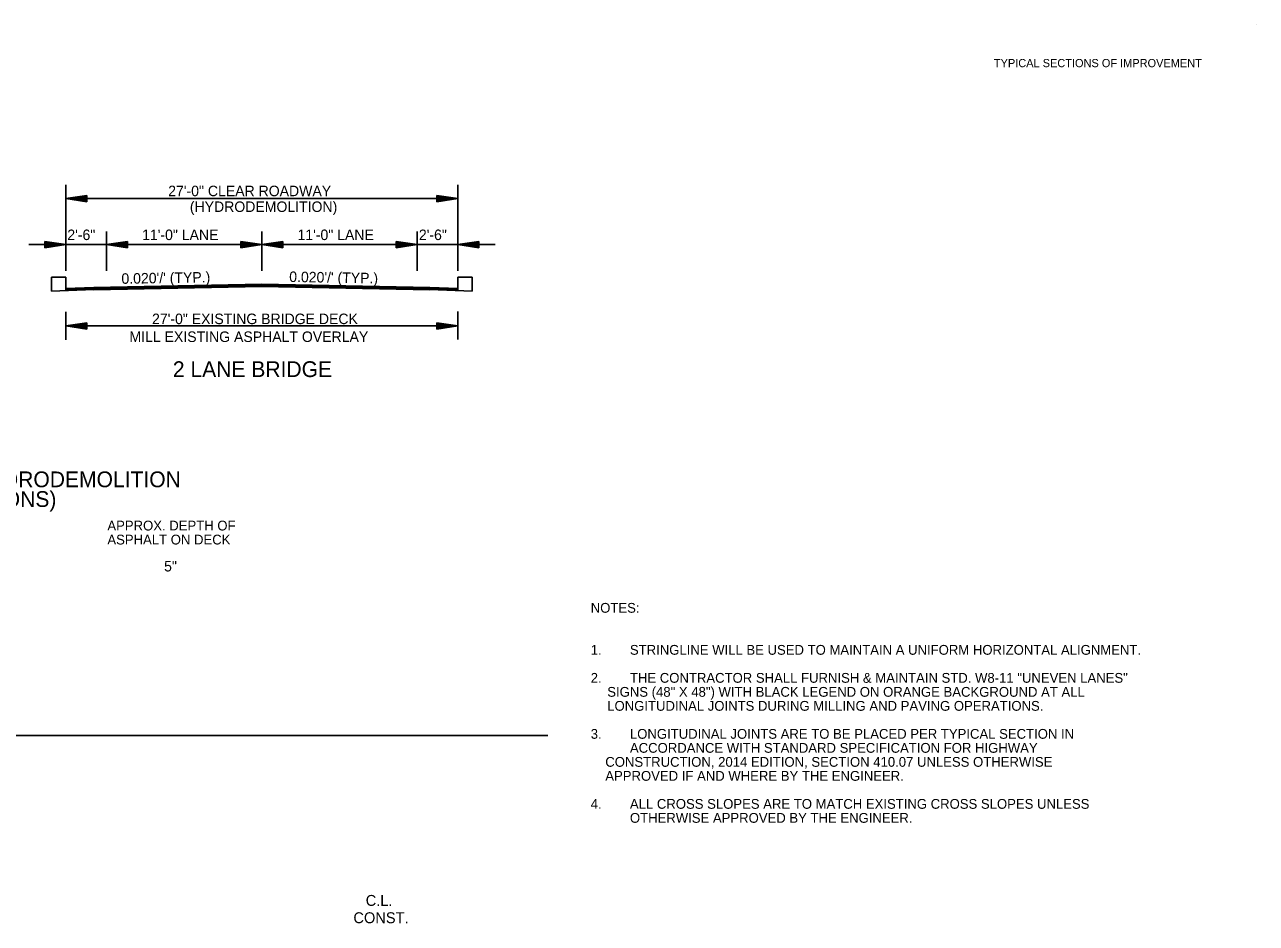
# Model space of a CAD drawing. Extents: x 549600 to 1930787, y -1955432 to 596640.
# Drawn here: x 551693 to 552572, y -1945052 to -1944410 of the extents above; entities that cross this region are included whole.
import ezdxf

# ---------------------------------------------------------------- set-up
doc = ezdxf.new("R2010")
doc.units = 0
for name, color, linetype in [('R_Border', 7, 'Continuous'), ('R_Border Notes', 7, 'Continuous'), ('R_Border Prem', 7, 'Continuous'), ('S_AREA_CALC', 7, 'Continuous')]:
    doc.layers.add(name, color=color, linetype=linetype)

msp = doc.modelspace()

# ---------------------------------------------------------------- linework, layer by layer
at = {"layer": 'R_Border'}
for p, q in [((551711.85, -1944590.68), (551711.85, -1944600.79)), ((551722.02, -1944590.68), (551711.85, -1944590.68)), ((551722.02, -1944600.09), (551722.02, -1944590.68)), ((552002.02, -1944600.09), (552002.02, -1944590.68)), ((552002.02, -1944590.68), (552012.18, -1944590.68)), ((552012.18, -1944590.68), (552012.18, -1944600.79)), ((551004.91, -1944917.94), (552066.18, -1944917.94))]:
    msp.add_line(p, q, dxfattribs=at)
at = {"layer": 'R_Border Prem'}
msp.add_line((552572.37, -1944410.35), (552572.37, -1944410.35), dxfattribs=at)
at = {"layer": 'S_AREA_CALC'}
for p, q in [((551722.02, -1944586.14), (551722.02, -1944524.65)), ((552002.02, -1944586.14), (552002.02, -1944524.65)), ((551737.02, -1944532.29), (551722.02, -1944534.54)), ((552002.02, -1944534.54), (551722.02, -1944534.54)), ((551737.02, -1944536.79), (551722.02, -1944534.54)), ((551737.02, -1944532.67), (551724.52, -1944534.54)), ((551737.02, -1944536.42), (551724.52, -1944534.54)), ((551737.02, -1944533.05), (551727.1, -1944534.54)), ((551737.02, -1944536.03), (551727.1, -1944534.54)), ((551737.02, -1944533.42), (551729.6, -1944534.54)), ((551737.02, -1944535.66), (551729.6, -1944534.54)), ((551737.02, -1944533.81), (551732.14, -1944534.54)), ((551737.02, -1944535.28), (551732.14, -1944534.54)), ((551737.02, -1944534.19), (551734.65, -1944534.54)), ((551737.02, -1944534.89), (551734.65, -1944534.54)), ((551737.02, -1944532.29), (551737.02, -1944536.79)), ((551987.02, -1944532.29), (552002.02, -1944534.54)), ((551987.02, -1944536.79), (551987.02, -1944532.29)), ((551987.02, -1944532.67), (551999.51, -1944534.54)), ((551987.02, -1944533.05), (551996.93, -1944534.54)), ((551987.02, -1944533.42), (551994.44, -1944534.54)), ((551987.02, -1944533.81), (551991.89, -1944534.54)), ((551987.02, -1944534.19), (551989.39, -1944534.54)), ((551987.02, -1944536.79), (552002.02, -1944534.54)), ((551987.02, -1944535.27), (551991.89, -1944534.54)), ((551987.02, -1944536.03), (551996.93, -1944534.54)), ((551987.02, -1944536.42), (551999.51, -1944534.54)), ((551987.02, -1944535.66), (551994.44, -1944534.54)), ((551987.02, -1944534.89), (551989.39, -1944534.54)), ((551751.02, -1944586.14), (551751.02, -1944558.19)), ((551862.02, -1944586.14), (551862.02, -1944558.19)), ((551973.02, -1944586.14), (551973.02, -1944558.19)), ((551722.02, -1944567.38), (551695.5, -1944567.38)), ((551707.02, -1944565.13), (551722.02, -1944567.38)), ((551707.02, -1944565.13), (551707.02, -1944569.63)), ((551707.02, -1944565.5), (551719.51, -1944567.38)), ((551707.02, -1944565.88), (551716.93, -1944567.38)), ((551707.02, -1944566.26), (551714.44, -1944567.38)), ((551707.02, -1944566.65), (551711.89, -1944567.38)), ((551707.02, -1944567.02), (551709.39, -1944567.38)), ((551707.02, -1944569.63), (551722.02, -1944567.38)), ((551707.02, -1944568.11), (551711.89, -1944567.38)), ((551707.02, -1944568.87), (551716.93, -1944567.38)), ((551707.02, -1944569.25), (551719.51, -1944567.38)), ((551707.02, -1944568.49), (551714.44, -1944567.38)), ((551707.02, -1944567.73), (551709.39, -1944567.38)), ((551751.02, -1944567.38), (551722.02, -1944567.38)), ((551766.02, -1944565.13), (551751.02, -1944567.38)), ((551862.02, -1944567.38), (551751.02, -1944567.38)), ((551766.02, -1944569.63), (551751.02, -1944567.38)), ((551766.02, -1944565.5), (551753.52, -1944567.38)), ((551766.02, -1944569.25), (551753.52, -1944567.38)), ((551766.02, -1944565.88), (551756.1, -1944567.38)), ((551766.02, -1944568.87), (551756.1, -1944567.38)), ((551766.02, -1944566.26), (551758.6, -1944567.38)), ((551766.02, -1944568.49), (551758.6, -1944567.38)), ((551766.02, -1944566.65), (551761.14, -1944567.38)), ((551766.02, -1944568.11), (551761.14, -1944567.38)), ((551766.02, -1944567.02), (551763.65, -1944567.38)), ((551766.02, -1944567.73), (551763.65, -1944567.38)), ((551766.02, -1944565.13), (551766.02, -1944569.63)), ((551847.02, -1944565.13), (551862.02, -1944567.38)), ((551847.02, -1944565.13), (551847.02, -1944569.63)), ((551847.02, -1944565.5), (551859.51, -1944567.38)), ((551847.02, -1944565.88), (551856.93, -1944567.38)), ((551847.02, -1944566.26), (551854.44, -1944567.38)), ((551847.02, -1944566.65), (551851.89, -1944567.38)), ((551847.02, -1944567.02), (551849.39, -1944567.38)), ((551847.02, -1944569.63), (551862.02, -1944567.38)), ((551847.02, -1944568.11), (551851.89, -1944567.38)), ((551847.02, -1944568.87), (551856.93, -1944567.38)), ((551847.02, -1944569.25), (551859.51, -1944567.38)), ((551847.02, -1944568.49), (551854.44, -1944567.38)), ((551847.02, -1944567.73), (551849.39, -1944567.38)), ((551877.02, -1944565.13), (551862.02, -1944567.38)), ((551973.02, -1944567.38), (551862.02, -1944567.38)), ((551877.02, -1944569.63), (551862.02, -1944567.38)), ((551877.02, -1944565.5), (551864.52, -1944567.38)), ((551877.02, -1944569.25), (551864.52, -1944567.38)), ((551877.02, -1944565.88), (551867.1, -1944567.38)), ((551877.02, -1944568.87), (551867.1, -1944567.38)), ((551877.02, -1944566.26), (551869.6, -1944567.38)), ((551877.02, -1944568.49), (551869.6, -1944567.38)), ((551877.02, -1944566.65), (551872.14, -1944567.38)), ((551877.02, -1944568.11), (551872.14, -1944567.38)), ((551877.02, -1944567.02), (551874.65, -1944567.38)), ((551877.02, -1944567.73), (551874.65, -1944567.38)), ((551877.02, -1944565.13), (551877.02, -1944569.63)), ((551958.02, -1944565.13), (551973.02, -1944567.38)), ((551958.02, -1944565.13), (551958.02, -1944569.63)), ((551958.02, -1944565.5), (551970.51, -1944567.38)), ((551958.02, -1944565.88), (551967.93, -1944567.38)), ((551958.02, -1944566.26), (551965.44, -1944567.38)), ((551958.02, -1944566.65), (551962.89, -1944567.38)), ((551958.02, -1944567.02), (551960.39, -1944567.38)), ((551958.02, -1944569.63), (551973.02, -1944567.38)), ((551958.02, -1944568.11), (551962.89, -1944567.38)), ((551958.02, -1944568.87), (551967.93, -1944567.38)), ((551958.02, -1944569.25), (551970.51, -1944567.38)), ((551958.02, -1944568.49), (551965.44, -1944567.38)), ((551958.02, -1944567.73), (551960.39, -1944567.38)), ((551973.02, -1944567.38), (552002.02, -1944567.38)), ((552017.02, -1944565.13), (552002.02, -1944567.38)), ((552017.02, -1944569.63), (552002.02, -1944567.38)), ((552028.54, -1944567.38), (552002.02, -1944567.38)), ((552017.02, -1944565.5), (552004.52, -1944567.38)), ((552017.02, -1944569.25), (552004.52, -1944567.38)), ((552017.02, -1944565.88), (552007.1, -1944567.38)), ((552017.02, -1944568.87), (552007.1, -1944567.38)), ((552017.02, -1944566.26), (552009.6, -1944567.38)), ((552017.02, -1944568.49), (552009.6, -1944567.38)), ((552017.02, -1944566.65), (552012.14, -1944567.38)), ((552017.02, -1944568.11), (552012.14, -1944567.38)), ((552017.02, -1944567.02), (552014.65, -1944567.38)), ((552017.02, -1944567.73), (552014.65, -1944567.38)), ((552017.02, -1944565.13), (552017.02, -1944569.63)), ((551862.02, -1944595.68), (551742.02, -1944598.08)), ((551862.02, -1944595.98), (551742.02, -1944598.38)), ((551862.02, -1944596.28), (551742.02, -1944598.68)), ((551862.02, -1944596.58), (551742.02, -1944598.98)), ((551862.02, -1944596.88), (551742.02, -1944599.28)), ((551862.02, -1944595.68), (551982.02, -1944598.08)), ((551862.02, -1944595.98), (551982.02, -1944598.38)), ((551862.02, -1944596.28), (551982.02, -1944598.68)), ((551862.02, -1944596.58), (551982.02, -1944598.98)), ((551862.02, -1944596.88), (551982.02, -1944599.28)), ((551742.02, -1944599.59), (551711.85, -1944600.79)), ((551742.02, -1944598.08), (551722.02, -1944598.88)), ((551742.02, -1944598.38), (551722.02, -1944599.18)), ((551742.02, -1944598.68), (551722.02, -1944599.48)), ((551742.02, -1944598.98), (551722.02, -1944599.78)), ((551742.02, -1944599.29), (551722.02, -1944600.09)), ((551862.02, -1944597.18), (551742.02, -1944599.58)), ((551862.02, -1944597.35), (551742.02, -1944599.75)), ((551862.02, -1944597.18), (551982.02, -1944599.58)), ((551862.02, -1944597.35), (551982.02, -1944599.75)), ((551982.02, -1944598.08), (552002.02, -1944598.88)), ((551982.02, -1944598.38), (552002.02, -1944599.18)), ((551982.02, -1944598.68), (552002.02, -1944599.48)), ((551982.02, -1944598.98), (552002.02, -1944599.78)), ((551982.02, -1944599.29), (552002.02, -1944600.09)), ((551982.02, -1944599.59), (552012.18, -1944600.79)), ((551722.02, -1944615.54), (551722.02, -1944635.54)), ((551737.02, -1944623.29), (551722.02, -1944625.54)), ((551737.02, -1944623.29), (551737.02, -1944627.79)), ((551987.02, -1944623.29), (552002.02, -1944625.54)), ((551987.02, -1944627.79), (551987.02, -1944623.29)), ((552002.02, -1944615.29), (552002.02, -1944635.29)), ((551737.02, -1944627.79), (551722.02, -1944625.54)), ((552002.02, -1944625.54), (551722.02, -1944625.54)), ((551737.02, -1944623.67), (551724.52, -1944625.54)), ((551737.02, -1944627.42), (551724.52, -1944625.54)), ((551737.02, -1944624.05), (551727.1, -1944625.54)), ((551737.02, -1944627.04), (551727.1, -1944625.54)), ((551737.02, -1944624.43), (551729.6, -1944625.54)), ((551737.02, -1944626.66), (551729.6, -1944625.54)), ((551737.02, -1944624.82), (551732.14, -1944625.54)), ((551737.02, -1944626.28), (551732.14, -1944625.54)), ((551737.02, -1944625.19), (551734.65, -1944625.54)), ((551737.02, -1944625.9), (551734.65, -1944625.54)), ((551987.02, -1944623.67), (551999.51, -1944625.54)), ((551987.02, -1944624.05), (551996.93, -1944625.54)), ((551987.02, -1944624.43), (551994.44, -1944625.54)), ((551987.02, -1944624.81), (551991.89, -1944625.54)), ((551987.02, -1944625.19), (551989.39, -1944625.54)), ((551987.02, -1944627.79), (552002.02, -1944625.54)), ((551987.02, -1944626.27), (551991.89, -1944625.54)), ((551987.02, -1944627.04), (551996.93, -1944625.54)), ((551987.02, -1944627.42), (551999.51, -1944625.54)), ((551987.02, -1944626.66), (551994.44, -1944625.54)), ((551987.02, -1944625.9), (551989.39, -1944625.54))]:
    msp.add_line(p, q, dxfattribs=at)

# ---------------------------------------------------------------- texts
at = {"layer": 'R_Border'}
for s, height, p in [('27 FT. CLEAR ROADWAY BRIDGE - HYDRODEMOLITION', 11.25, (551401.23, -1944740.7)), ('(ROADWAY TRANSITIONS)', 11.25, (551522.18, -1944754.78)), ('5"', 7.5, (551792.18, -1944800.86))]:
    msp.add_text(s, height=height, dxfattribs=at).set_placement(p)
at = {"layer": 'R_Border Notes'}
for s, p in [('APPROX. DEPTH OF', (551751.65, -1944771.6)), ('ASPHALT ON DECK', (551751.65, -1944781.6)), ('NOTES: ', (552096.91, -1944830.35)), ('1.', (552096.91, -1944860.35)), ('STRINGLINE WILL BE USED TO MAINTAIN A UNIFORM HORIZONTAL ALIGNMENT.', (552124.91, -1944860.35)), ('2.', (552096.91, -1944880.35)), ('THE CONTRACTOR SHALL FURNISH & MAINTAIN STD. W8-11 "UNEVEN LANES" ', (552124.91, -1944880.35)), ('    SIGNS (48" X 48") WITH BLACK LEGEND ON ORANGE BACKGROUND AT ALL ', (552098.31, -1944890.35)), ('    LONGITUDINAL JOINTS DURING MILLING AND PAVING OPERATIONS.', (552098.31, -1944900.35)), ('3.', (552096.91, -1944920.35)), ('LONGITUDINAL JOINTS ARE TO BE PLACED PER TYPICAL SECTION IN ', (552124.91, -1944920.35)), ('ACCORDANCE WITH STANDARD SPECIFICATION FOR HIGHWAY', (552124.91, -1944930.35)), ('    CONSTRUCTION, 2014 EDITION, SECTION 410.07 UNLESS OTHERWISE', (552096.91, -1944940.35)), ('    APPROVED IF AND WHERE BY THE ENGINEER.', (552096.91, -1944950.35)), ('4.', (552096.91, -1944970.35)), ('ALL CROSS SLOPES ARE TO MATCH EXISTING CROSS SLOPES UNLESS ', (552124.91, -1944970.35)), ('OTHERWISE APPROVED BY THE ENGINEER.', (552124.91, -1944980.35))]:
    msp.add_text(s, height=7, dxfattribs=at).set_placement(p)
at = {"layer": 'R_Border Prem'}
msp.add_text('TYPICAL SECTIONS OF IMPROVEMENT', height=5.862, rotation=360, dxfattribs=at).set_placement((552384.89, -1944440.73))
at = {"layer": 'S_AREA_CALC'}
for s, height, p in [('27\'-0" CLEAR ROADWAY', 7.5, (551795.11, -1944532.87)), ('(HYDRODEMOLITION)', 7.5, (551810.58, -1944544.12)), ('2\'-6"', 7.5, (551723.04, -1944564.2)), ('11\'-0" LANE', 7.5, (551776.46, -1944564.2)), ('11\'-0" LANE', 7.5, (551887.46, -1944564.2)), ('2\'-6"', 7.5, (551974.17, -1944564.2)), ('27\'-0" EXISTING BRIDGE DECK', 7.5, (551783.57, -1944624.22)), ('MILL EXISTING ASPHALT OVERLAY', 7.5, (551767.44, -1944636.98)), ('2 LANE BRIDGE ', 11.25, (551798.45, -1944662.01)), ('C.L.', 7.8, (551936.17, -1945039.69)), ('CONST.', 7.8, (551927.39, -1945052.06))]:
    msp.add_text(s, height=height, dxfattribs=at).set_placement(p)
for rotation, p in [(0.97192, (551761.76, -1944595.48)), (359.02808, (551881.5, -1944594.11))]:
    msp.add_text("0.020'/' (TYP.)", height=7.5, rotation=rotation, dxfattribs=at).set_placement(p)

doc.saveas('drawing.dxf')
